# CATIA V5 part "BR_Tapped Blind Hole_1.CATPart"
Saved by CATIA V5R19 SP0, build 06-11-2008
Bounding box of the stored display mesh (mm): x 26.3 to 38.284, y -78.933 to -67.113, z -22.454 to 0
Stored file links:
  C:\Program Files\Dassault Systemes\Power Feature\SampleData\SharedData\BusinessRules\BR_RulesPart\BR_Tapped Blind Hole_1.CATPart
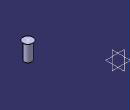
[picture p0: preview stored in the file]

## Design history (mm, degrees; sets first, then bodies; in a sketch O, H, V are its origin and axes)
Set1
  Point1: type OnPlane, Support xy-plane, Direction (1, 0, 0), H 32.292, V -73.023
Body1 (main body)
  UdfFeature1 "Tapped Blind Hole": UdfInputSpec1 AxisSystem1, DG 10, TG 15, DK 8.5, TK 20, DF 12, W 90, SR "RH", P 1.5, SW 120, AS_H 0, AS_D 0, StandardType "No Standard", InternalVersion 1, Through false, UIHidden_zDK 4.25 {= Body2.DK / 2}, UIHidden_zDF 6 {= Body2.DF / 2}
Body2 "UDF_Body"
  AxisSystem1 "MainAxisSystem": origin (32.292, -73.023, 0), X (-1, 0, 0), Y (0, -1, 0), Z (0, 0, 1)
  Sketch1 "MainProfileSketch" on ZX plane of AxisSystem1, origin (32.292, -73.023, 0), H (1, 0, 0), V (0, 0, 1)
    axis line L1 (0, 0) -> (0, -22.4537)
    point P2 (0, -22.4537)
    line L2 (0, -22.4537) -> (4.25, -20)
    point P3 (4.25, -20)
    line L3 (4.25, -20) -> (4.25, -1.75)
    line L4 (4.25, -1.75) -> (6, 0)
    point P4 (6, 0)
    line L5 (6, 0) -> (6, 0)
    line L6 (6, 0) -> (6, 0)
    line L7 (6, 0) -> (0, 0)
    point P7 (-4.25, -20)
    point P8 (0, -22.4537)
    construction line L8 (0, -22.4537) -> (-4.25, -20)
    construction line L9 (6, 0) -> (0, 0)
    reference projected line E1 through (0, 0) direction (-1, 0) from edge [XY plane of AxisSystem1 | ZX plane of AxisSystem1]
    reference projected line E2 through (0, 0) direction (-1, 0) from edge [XY plane of AxisSystem1 | ZX plane of AxisSystem1]
    reference projected line E3 through (0, 0) direction (-1, 0) from edge [XY plane of AxisSystem1 | ZX plane of AxisSystem1]
    reference projected line E4 through (0, 0) direction (0, 1) from edge [ZX plane of AxisSystem1 | YZ plane of AxisSystem1]
    point P9 (4.25, -1.75)
    point P10 (-6, 0)
    point P11 (-4.25, -1.75)
    construction line L10 (-4.25, -1.75) -> (-6, 0)
    angle L4 L10 = 90
    "UIHidden_zDK" L1 L3 = 4.25 {= Body2.DK / 2}
    angle L2 L8 = 120
    distance E1 P3 = 20
    length L9 = 6 {= sqrt((Body2.AS_H * Body2.AS_H ) + ((Sketch1.UIHidden_zDF(L1 P4) + Groove1.AS_ZR ) * (Sketch1.UIHidden_zDF(L1 P4) + Groove1.AS_ZR )))}
    angle L9 L5 = 0 {= atan(Body2.AS_H / (Sketch1.UIHidden_zDF(L1 P4) + Groove1.AS_ZR ))}
    "UIHidden_zDF" L1 P4 = 6 {= Body2.DF / 2}
    coincidence: E2 L5, L1 E4
    symmetry: P3 P7 L1, P2 P8 L1, L2 L8 L1, P4 P10 L1, P9 P11 L1, L4 L10 L1
    perpendicularity: L1 L7, E3 L6
  Groove1 "MainGroove": profile Sketch1, axis Sketch1.L1, angle 360
  Thread1 "Tap": diameter 10, depth 15, pitch 1.5, on face of Groove1 from Sketch1.L3, from {plane type Normal, Curve edge [ZX plane of AxisSystem1 | YZ plane of AxisSystem1], RefPoint vertex [YZ plane of AxisSystem1 | ZX plane of AxisSystem1 | XY plane of AxisSystem1]}
Relations
  Body2.W = Sketch1.angle(L4 L10)
  Body2.TK = Sketch1.distance(E1 P3)
  Body2.SW = Sketch1.angle(L2 L8)
  Groove1.top_width = Body2.DF
  rule "AS_ZR":
    /*Rule created by AKNOPP 30.06.2006*/
    Groove1.AS_ZR = Body2.AS_D - (2 * Sketch1.UIHidden_zDF(L1 P4))
    if (Body2.AS_D == 0mm)
    {
    	Groove1.AS_ZR = 0mm
    }
    else
    	Groove1.AS_ZR = (Body2.AS_D / 2) - Sketch1.UIHidden_zDF(L1 P4)
  Body2.P = Thread1.P
  Body2.GB = Thread1.GB
  Body2.DG = Thread1.DG
  Body2.TG = Thread1.TG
